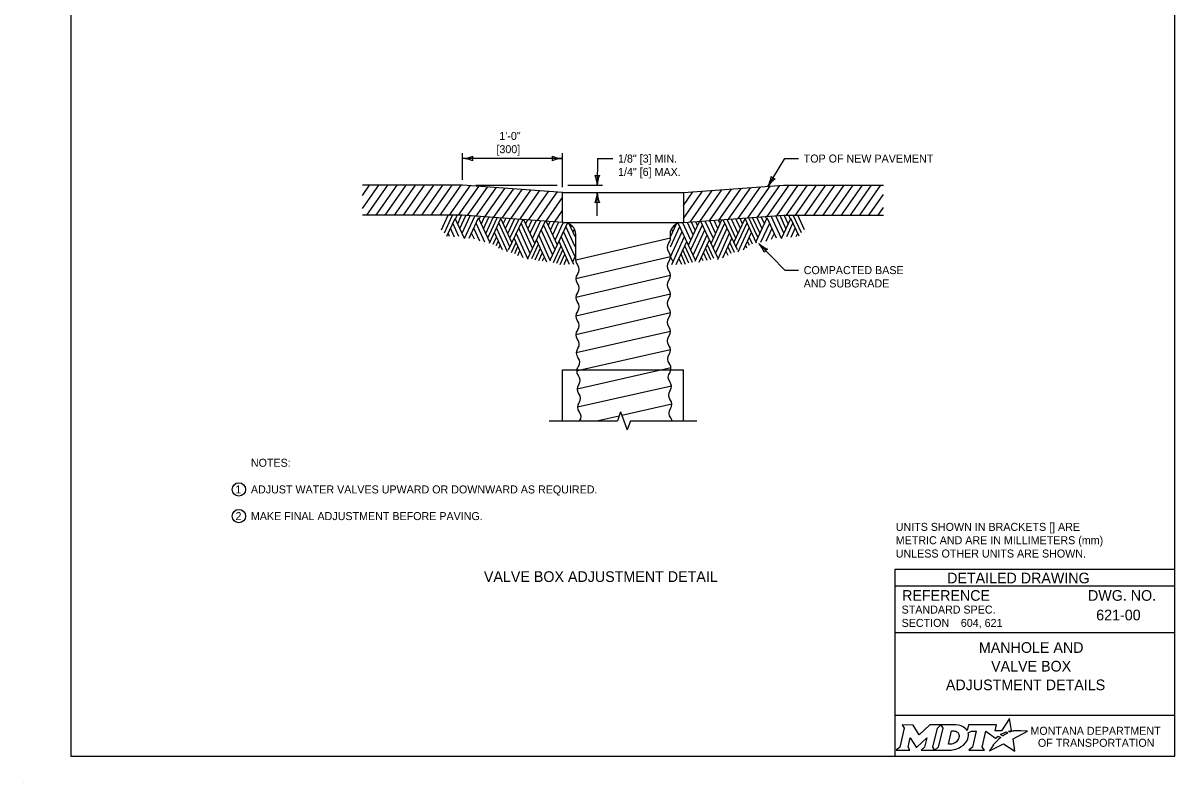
# Model space of a CAD drawing. Extents: x 49991.4 to 50021, y 49987.6 to 50011.4.
# Drawn here: x 49999.98 to 50008.61, y 49999.86 to 50005.56 of the extents above; entities that cross this region are included whole.
import ezdxf

# ---------------------------------------------------------------- set-up
doc = ezdxf.new("R2010")
doc.units = 0
for name, color, linetype in [('Level 1', 7, 'Continuous'), ('Level 2', 7, 'Continuous'), ('Level 3', 7, 'Continuous'), ('Level 4', 7, 'Continuous'), ('Level 6', 7, 'Continuous')]:
    doc.layers.add(name, color=color, linetype=linetype)

msp = doc.modelspace()

# ---------------------------------------------------------------- linework, layer by layer
at = {"layer": 'Level 1'}
for p, q in [((50003.2717, 50004.346), (50002.5217, 50004.346)), ((50002.5217, 50004.2687), (50002.5758, 50004.346)), ((50002.5217, 50004.1707), (50002.6445, 50004.346)), ((50002.5556, 50004.121), (50002.7132, 50004.346)), ((50002.6243, 50004.121), (50002.7818, 50004.346)), ((50002.693, 50004.121), (50002.8506, 50004.346)), ((50002.7616, 50004.121), (50002.9192, 50004.346)), ((50002.8303, 50004.121), (50002.9879, 50004.346)), ((50002.899, 50004.121), (50003.0565, 50004.346)), ((50002.9676, 50004.121), (50003.1252, 50004.346)), ((50003.0363, 50004.121), (50003.1938, 50004.346)), ((50003.105, 50004.121), (50003.2625, 50004.346)), ((50004.0217, 50004.2904), (50003.2717, 50004.346)), ((50004.9285, 50004.2904), (50005.6785, 50004.346)), ((50005.5577, 50004.112), (50005.7215, 50004.346)), ((50005.6301, 50004.1173), (50005.7902, 50004.346)), ((50005.6785, 50004.346), (50006.4285, 50004.346)), ((50005.7014, 50004.121), (50005.8589, 50004.346)), ((50005.77, 50004.121), (50005.9275, 50004.346)), ((50005.8387, 50004.121), (50005.9963, 50004.346)), ((50005.9074, 50004.121), (50006.0649, 50004.346)), ((50005.976, 50004.121), (50006.1336, 50004.346)), ((50006.0447, 50004.121), (50006.2022, 50004.346)), ((50006.1133, 50004.121), (50006.2709, 50004.346)), ((50006.182, 50004.121), (50006.3396, 50004.346)), ((50006.2507, 50004.121), (50006.4082, 50004.346)), ((50003.1736, 50004.121), (50003.3284, 50004.3418)), ((50003.2424, 50004.121), (50003.3935, 50004.337)), ((50003.309, 50004.1182), (50003.4588, 50004.3321)), ((50003.3743, 50004.1133), (50003.5241, 50004.3273)), ((50003.4396, 50004.1085), (50003.5893, 50004.3225)), ((50003.5048, 50004.1037), (50003.6547, 50004.3176)), ((50003.5701, 50004.0988), (50003.7199, 50004.3128)), ((50003.6354, 50004.094), (50003.7853, 50004.3079)), ((50003.7007, 50004.0892), (50003.8505, 50004.3031)), ((50003.766, 50004.0843), (50003.9157, 50004.2983)), ((50003.8312, 50004.0795), (50003.9811, 50004.2934)), ((50004.0217, 50004.2904), (50004.9285, 50004.2904)), ((50004.0217, 50004.0654), (50004.0217, 50004.2904)), ((50004.9285, 50004.0961), (50005.072, 50004.301)), ((50004.9285, 50004.1941), (50004.9995, 50004.2957)), ((50004.9285, 50004.2904), (50004.9285, 50004.0654)), ((50004.9784, 50004.0691), (50005.1444, 50004.3064)), ((50005.0507, 50004.0744), (50005.2169, 50004.3118)), ((50005.1232, 50004.0798), (50005.2894, 50004.3172)), ((50005.1956, 50004.0852), (50005.3618, 50004.3225)), ((50005.2679, 50004.0905), (50005.4343, 50004.3279)), ((50005.3403, 50004.0959), (50005.5066, 50004.3333)), ((50005.4128, 50004.1013), (50005.579, 50004.3386)), ((50005.4853, 50004.1066), (50005.6515, 50004.344)), ((50006.3193, 50004.121), (50006.4285, 50004.2769)), ((50003.8966, 50004.0747), (50004.0217, 50004.2535)), ((50006.3881, 50004.121), (50006.4285, 50004.1788)), ((50003.2707, 50004.121), (50002.5217, 50004.121)), ((50003.1144, 50004.0125), (50003.1645, 50004.121)), ((50003.1361, 50003.9884), (50003.1977, 50004.121)), ((50003.1545, 50003.964), (50003.217, 50004.0974)), ((50003.2863, 50003.9474), (50003.217, 50004.0974)), ((50003.2193, 50004.0924), (50003.2323, 50004.121)), ((50003.2359, 50004.0565), (50003.2653, 50004.121)), ((50003.2529, 50004.0214), (50003.2973, 50004.119)), ((50003.2689, 50003.9856), (50003.3292, 50004.1167)), ((50004.0217, 50004.0654), (50003.2707, 50004.121)), ((50003.2864, 50003.9475), (50003.3637, 50004.1141)), ((50003.3226, 50003.9497), (50003.393, 50004.1008)), ((50003.4773, 50003.9185), (50003.393, 50004.1007)), ((50003.3972, 50004.0916), (50003.4061, 50004.111)), ((50003.4138, 50004.0558), (50003.4379, 50004.1086)), ((50003.4304, 50004.0199), (50003.4699, 50004.1063)), ((50003.4468, 50003.9844), (50003.5027, 50004.1038)), ((50003.4744, 50003.9121), (50003.5596, 50004.0967)), ((50003.4891, 50004.0096), (50003.5313, 50004.1017)), ((50003.6428, 50003.9163), (50003.5596, 50004.0967)), ((50003.5782, 50004.0565), (50003.5967, 50004.0969)), ((50003.5946, 50004.0203), (50003.6286, 50004.0945)), ((50003.6117, 50003.9833), (50003.6618, 50004.092)), ((50003.6168, 50003.8606), (50003.7232, 50004.0875)), ((50003.6281, 50003.9479), (50003.694, 50004.0897)), ((50003.8147, 50003.9095), (50003.7328, 50004.0868)), ((50003.9618, 50004.0698), (50004.0217, 50004.1553)), ((50004.9285, 50004.0654), (50005.6795, 50004.121)), ((50004.9285, 50004.0654), (50005.6795, 50004.121)), ((50005.1355, 50003.9095), (50005.2174, 50004.0868)), ((50005.3334, 50003.8606), (50005.227, 50004.0875)), ((50005.3221, 50003.9479), (50005.2562, 50004.0897)), ((50005.3385, 50003.9833), (50005.2884, 50004.092)), ((50005.3074, 50003.9163), (50005.3906, 50004.0967)), ((50005.3556, 50004.0203), (50005.3216, 50004.0945)), ((50005.372, 50004.0565), (50005.3535, 50004.0969)), ((50005.4758, 50003.9121), (50005.3906, 50004.0967)), ((50005.4611, 50004.0096), (50005.4189, 50004.1017)), ((50005.5034, 50003.9844), (50005.4475, 50004.1038)), ((50005.4729, 50003.9185), (50005.5572, 50004.1007)), ((50005.5198, 50004.0199), (50005.4803, 50004.1063)), ((50005.5364, 50004.0558), (50005.5123, 50004.1086)), ((50005.553, 50004.0916), (50005.5441, 50004.111)), ((50005.6276, 50003.9497), (50005.5572, 50004.1008)), ((50005.6638, 50003.9475), (50005.5865, 50004.1141)), ((50005.6813, 50003.9856), (50005.621, 50004.1167)), ((50005.6973, 50004.0214), (50005.6529, 50004.119)), ((50005.6639, 50003.9474), (50005.7332, 50004.0974)), ((50005.6795, 50004.121), (50006.4285, 50004.121)), ((50005.7143, 50004.0565), (50005.6849, 50004.121)), ((50005.7309, 50004.0924), (50005.7179, 50004.121)), ((50005.7957, 50003.964), (50005.7332, 50004.0974)), ((50005.8141, 50003.9884), (50005.7525, 50004.121)), ((50005.8358, 50004.0125), (50005.7857, 50004.121)), ((50003.2128, 50003.9576), (50003.1824, 50004.0237)), ((50003.2455, 50003.9623), (50003.1999, 50004.0606)), ((50003.4018, 50003.9269), (50003.3569, 50004.0237)), ((50003.4406, 50003.9188), (50003.3744, 50004.061)), ((50003.4621, 50003.9517), (50003.4891, 50004.0096)), ((50003.6104, 50003.847), (50003.5279, 50004.0275)), ((50003.6274, 50003.8834), (50003.5447, 50004.063)), ((50003.7799, 50003.8348), (50003.6933, 50004.0237)), ((50003.7978, 50003.8732), (50003.7108, 50004.0607)), ((50003.7468, 50004.0565), (50003.7596, 50004.0848)), ((50003.7615, 50003.7952), (50003.8918, 50004.075)), ((50003.7638, 50004.0214), (50003.7914, 50004.0825)), ((50003.7798, 50003.9856), (50003.8232, 50004.0801)), ((50003.7972, 50003.9473), (50003.8575, 50004.0776)), ((50003.9485, 50003.8223), (50003.8619, 50004.0112)), ((50003.9664, 50003.8607), (50003.8794, 50004.0482)), ((50003.9833, 50003.897), (50003.9014, 50004.0743)), ((50003.9154, 50004.044), (50003.9282, 50004.0723)), ((50003.9301, 50003.7827), (50004.0597, 50004.0609)), ((50003.9324, 50004.0089), (50003.96, 50004.07)), ((50003.9484, 50003.9731), (50003.9918, 50004.0676)), ((50003.9658, 50003.9348), (50004.0261, 50004.0651)), ((50004.0217, 50004.0654), (50004.9285, 50004.0654)), ((50004.1179, 50003.8851), (50004.048, 50004.0357)), ((50004.1179, 50003.9581), (50004.073, 50004.0554)), ((50004.084, 50004.0315), (50004.0897, 50004.0442)), ((50004.101, 50003.9964), (50004.1109, 50004.0182)), ((50004.8323, 50003.9581), (50004.8772, 50004.0554)), ((50004.8323, 50003.8851), (50004.9022, 50004.0357)), ((50004.8323, 50003.9491), (50004.8323, 50004.0014)), ((50004.8492, 50003.9964), (50004.8393, 50004.0182)), ((50004.8662, 50004.0315), (50004.8605, 50004.0442)), ((50005.0201, 50003.7827), (50004.8905, 50004.0609)), ((50004.9844, 50003.9348), (50004.9241, 50004.0651)), ((50005.0018, 50003.9731), (50004.9584, 50004.0676)), ((50004.9669, 50003.897), (50005.0488, 50004.0743)), ((50004.9838, 50003.8607), (50005.0708, 50004.0482)), ((50005.0178, 50004.0089), (50004.9902, 50004.07)), ((50005.0017, 50003.8223), (50005.0883, 50004.0112)), ((50005.0348, 50004.044), (50005.022, 50004.0723)), ((50005.1887, 50003.7952), (50005.0584, 50004.075)), ((50005.153, 50003.9473), (50005.0927, 50004.0776)), ((50005.1704, 50003.9856), (50005.127, 50004.0801)), ((50005.1524, 50003.8732), (50005.2394, 50004.0607)), ((50005.1864, 50004.0214), (50005.1588, 50004.0825)), ((50005.1703, 50003.8348), (50005.2569, 50004.0237)), ((50005.2034, 50004.0565), (50005.1906, 50004.0848)), ((50005.3228, 50003.8834), (50005.4055, 50004.063)), ((50005.3398, 50003.847), (50005.4223, 50004.0275)), ((50005.4881, 50003.9517), (50005.4611, 50004.0096)), ((50005.5096, 50003.9188), (50005.5758, 50004.061)), ((50005.5484, 50003.9269), (50005.5933, 50004.0237)), ((50005.7047, 50003.9623), (50005.7503, 50004.0606)), ((50005.7374, 50003.9576), (50005.7678, 50004.0237)), ((50003.1752, 50003.9617), (50003.1645, 50003.9852)), ((50003.3608, 50003.9406), (50003.3398, 50003.9863)), ((50003.5026, 50003.9029), (50003.5275, 50003.9573)), ((50003.5713, 50003.8614), (50003.5115, 50003.9925)), ((50003.5257, 50003.8927), (50003.5414, 50003.927)), ((50003.6396, 50003.842), (50003.6737, 50003.9164)), ((50003.7261, 50003.8008), (50003.6585, 50003.9498)), ((50003.7638, 50003.7901), (50003.6754, 50003.9852)), ((50003.9037, 50003.7684), (50003.8271, 50003.9373)), ((50003.9324, 50003.7776), (50003.844, 50003.9727)), ((50004.0749, 50003.7502), (50003.9957, 50003.9248)), ((50004.1077, 50003.7503), (50004.0126, 50003.9602)), ((50004.1179, 50003.8081), (50004.0305, 50003.9987)), ((50004.1217, 50003.7842), (50004.1217, 50003.9754)), ((50004.8323, 50003.9491), (50004.1217, 50003.7842)), ((50004.8323, 50003.8081), (50004.9197, 50003.9987)), ((50004.8425, 50003.7503), (50004.9376, 50003.9602)), ((50004.8753, 50003.7502), (50004.9545, 50003.9248)), ((50005.0178, 50003.7776), (50005.1062, 50003.9727)), ((50005.0465, 50003.7684), (50005.1231, 50003.9373)), ((50005.1864, 50003.7901), (50005.2748, 50003.9852)), ((50005.2241, 50003.8008), (50005.2917, 50003.9498)), ((50005.3106, 50003.842), (50005.2765, 50003.9164)), ((50005.3789, 50003.8614), (50005.4387, 50003.9925)), ((50005.4245, 50003.8927), (50005.4088, 50003.927)), ((50005.4476, 50003.9029), (50005.4227, 50003.9573)), ((50005.5894, 50003.9406), (50005.6104, 50003.9863)), ((50005.775, 50003.9617), (50005.7857, 50003.9852)), ((50003.5448, 50003.8746), (50003.5551, 50003.897)), ((50003.6635, 50003.8328), (50003.6876, 50003.8856)), ((50003.6867, 50003.8186), (50003.7024, 50003.853)), ((50003.7927, 50003.7957), (50003.8423, 50003.9039)), ((50003.8165, 50003.7861), (50003.8562, 50003.8731)), ((50003.8442, 50003.7818), (50003.871, 50003.8405)), ((50003.9536, 50003.7664), (50004.0109, 50003.8914)), ((50003.9798, 50003.7621), (50004.0248, 50003.8606)), ((50004.0052, 50003.7525), (50004.0396, 50003.828)), ((50004.945, 50003.7525), (50004.9106, 50003.828)), ((50004.9704, 50003.7621), (50004.9254, 50003.8606)), ((50004.9966, 50003.7664), (50004.9393, 50003.8914)), ((50005.106, 50003.7818), (50005.0792, 50003.8405)), ((50005.1337, 50003.7861), (50005.094, 50003.8731)), ((50005.1575, 50003.7957), (50005.1079, 50003.9039)), ((50005.2635, 50003.8186), (50005.2478, 50003.853)), ((50005.2867, 50003.8328), (50005.2626, 50003.8856)), ((50005.4054, 50003.8746), (50005.3951, 50003.897)), ((50003.8728, 50003.7779), (50003.8851, 50003.805)), ((50004.0332, 50003.7509), (50004.0525, 50003.7932)), ((50004.0987, 50003.7702), (50004.1179, 50003.8114)), ((50004.8323, 50003.8091), (50004.1217, 50003.6442)), ((50004.8515, 50003.7702), (50004.8323, 50003.8114)), ((50004.917, 50003.7509), (50004.8977, 50003.7932)), ((50005.0774, 50003.7779), (50005.0651, 50003.805)), ((50004.8323, 50003.6691), (50004.1217, 50003.5042)), ((50004.8323, 50003.5291), (50004.1217, 50003.3642)), ((50004.8323, 50003.3891), (50004.1217, 50003.2242)), ((50004.8323, 50003.2491), (50004.1249, 50003.0883)), ((50004.8322, 50003.1117), (50004.1667, 50002.9611)), ((50004.8354, 50002.9758), (50004.7706, 50002.9611)), ((50004.0217, 50002.9611), (50004.9285, 50002.9611)), ((50004.0217, 50002.5787), (50004.0217, 50002.9611)), ((50004.9285, 50002.5787), (50004.9285, 50002.9611)), ((49999.9766, 49999.8624), (49999.9766, 49999.8624))]:
    msp.add_line(p, q, dxfattribs=at)
msp.add_lwpolyline([(50008.6146, 50011.2628), (50000.3356, 50011.2628), (50000.3356, 50000.0624), (50008.6146, 50000.0624)], close=True, dxfattribs=at)
for centre, radius, start, end in [((50004.0317, 50003.9754), 0.09, 0, 90), ((50004.9185, 50003.9754), 0.09, 90, 163.23954), ((50004.8594, 50003.8791), 0.0533, 138.95969, 221.04031), ((50004.779, 50003.9491), 0.0533, 318.95969, 0), ((50004.779, 50003.8091), 0.0533, 318.95969, 41.04031), ((50004.175, 50003.7842), 0.0533, 180, 221.04031), ((50004.0946, 50003.7142), 0.0533, 318.95969, 41.04031), ((50004.8594, 50003.7391), 0.0533, 138.95969, 221.04031), ((50004.175, 50003.6442), 0.0533, 138.95969, 221.04031), ((50004.779, 50003.6691), 0.0533, 318.95969, 41.04031), ((50004.0946, 50003.5742), 0.0533, 318.95969, 41.04031), ((50004.8594, 50003.5991), 0.0533, 138.95969, 221.04031), ((50004.175, 50003.5042), 0.0533, 138.95969, 221.04031), ((50004.8594, 50003.4591), 0.0533, 138.95969, 221.04031), ((50004.779, 50003.5291), 0.0533, 318.95969, 41.04031), ((50004.175, 50003.3642), 0.0533, 138.95969, 221.04031), ((50004.0946, 50003.4342), 0.0533, 318.95969, 41.04031), ((50004.779, 50003.3891), 0.0533, 318.95969, 41.04031), ((50004.0946, 50003.2942), 0.0533, 318.95969, 41.04031), ((50004.8594, 50003.3191), 0.0533, 138.95969, 221.04031), ((50004.175, 50003.2242), 0.0533, 138.95969, 221.04031), ((50004.779, 50003.2491), 0.0533, 318.95969, 41.04031), ((50004.0946, 50003.1542), 0.0533, 324.57936, 41.04031), ((50004.8594, 50003.1791), 0.0533, 138.95969, 221.04031), ((50004.779, 50003.1091), 0.0533, 324.57936, 41.04031), ((50004.1782, 50003.0883), 0.0533, 138.95969, 221.04031), ((50004.0978, 50003.0183), 0.0533, 324.57936, 41.04031), ((50004.8626, 50003.0432), 0.0533, 138.95969, 221.04031), ((50004.1814, 50002.9524), 0.0533, 138.95969, 170.60676), ((50004.7822, 50002.9732), 0.0533, 346.87993, 41.04031)]:
    msp.add_arc(centre, radius, start, end, dxfattribs=at)
at = {"layer": 'Level 2'}
for p, q in [((50008.6146, 50001.4624), (50006.5146, 50001.4624)), ((50006.5146, 50001.4624), (50006.5146, 50000.0624)), ((50008.6146, 50001.3374), (50006.5146, 50001.3374)), ((50008.2507, 50001.1223), (50008.2507, 50001.1223)), ((50008.6146, 50000.9874), (50006.5146, 50000.9874)), ((50007.0089, 50001.0629), (50007.0089, 50001.0629)), ((50007.5646, 50000.7383), (50007.5646, 50000.7383)), ((50008.6146, 50000.3693), (50006.5146, 50000.3693))]:
    msp.add_line(p, q, dxfattribs=at)
for points in [[(50006.5701, 50000.2974), (50006.5842, 50000.274), (50006.5507, 50000.1307), (50006.525, 50000.1082), (50006.6266, 50000.1082), (50006.6131, 50000.131), (50006.6293, 50000.2011), (50006.673, 50000.1321), (50006.6783, 50000.1321), (50006.7534, 50000.2016), (50006.737, 50000.1305), (50006.7123, 50000.1085), (50006.8139, 50000.1085), (50006.8001, 50000.1318), (50006.8333, 50000.2742)], [(50006.8333, 50000.2742), (50006.8586, 50000.2974), (50006.7762, 50000.2974), (50006.6966, 50000.2244), (50006.6521, 50000.2971), (50006.5701, 50000.2974)], [(50006.9722, 50000.2974), (50006.8586, 50000.2974), (50006.8733, 50000.2745), (50006.8394, 50000.1307), (50006.8139, 50000.1085), (50006.9245, 50000.1085)], [(50007.3771, 50000.2447), (50007.3668, 50000.2503), (50007.3784, 50000.2531), (50007.39, 50000.2551), (50007.3726, 50000.3452), (50007.3131, 50000.2539), (50007.2658, 50000.2532), (50007.2761, 50000.2973), (50007.0669, 50000.2974), (50007.0568, 50000.2549), (50007.051, 50000.2632)], [(50006.9962, 50000.2107), (50006.995, 50000.2026), (50006.9918, 50000.1933), (50006.9876, 50000.1851), (50006.982, 50000.1776), (50006.9755, 50000.1707), (50006.9676, 50000.1644), (50006.9593, 50000.1597), (50006.9502, 50000.1558), (50006.9411, 50000.1535), (50006.9319, 50000.1526), (50006.916, 50000.1526), (50006.9396, 50000.2526), (50006.9556, 50000.2526), (50006.9632, 50000.252), (50006.9708, 50000.2501), (50006.9774, 50000.2471), (50006.9835, 50000.2429), (50006.9883, 50000.2379), (50006.992, 50000.2319), (50006.9947, 50000.2257), (50006.9963, 50000.2183), (50006.9963, 50000.2153), (50006.9962, 50000.2107)], [(50007.0636, 50000.2383), (50007.0882, 50000.2514), (50007.1251, 50000.2514), (50007.0965, 50000.1309), (50007.069, 50000.1082), (50007.1852, 50000.1082), (50007.1682, 50000.1311), (50007.1964, 50000.2513), (50007.2677, 50000.1996), (50007.2888, 50000.2147), (50007.3085, 50000.2038)], [(50007.2527, 50000.1479), (50007.2374, 50000.1235), (50007.2327, 50000.116), (50007.2269, 50000.1074), (50007.2246, 50000.1031), (50007.3299, 50000.1562), (50007.4138, 50000.1011), (50007.4007, 50000.1938), (50007.5076, 50000.2522), (50007.4583, 50000.253), (50007.4282, 50000.2534), (50007.4074, 50000.2537), (50007.4006, 50000.2522), (50007.3957, 50000.251), (50007.3873, 50000.2487), (50007.3771, 50000.2447)], [(50007.3267, 50000.2171), (50007.3243, 50000.2154), (50007.306, 50000.225), (50007.3163, 50000.2307), (50007.3204, 50000.2329), (50007.329, 50000.2369), (50007.3347, 50000.2395), (50007.3426, 50000.2425), (50007.3499, 50000.2452), (50007.3617, 50000.2378), (50007.3577, 50000.2357), (50007.3531, 50000.2332), (50007.3489, 50000.231), (50007.3439, 50000.2281), (50007.342, 50000.227), (50007.3393, 50000.2254), (50007.3368, 50000.224), (50007.3345, 50000.2224), (50007.3319, 50000.2206), (50007.3292, 50000.2188), (50007.3267, 50000.2171)], [(50006.9702, 50000.1158), (50006.9786, 50000.1184), (50006.9916, 50000.1238), (50007.012, 50000.1348)], [(50007.2666, 50000.164), (50007.2666, 50000.164)]]:
    msp.add_lwpolyline(points, dxfattribs=at)
for centre in [(50001.5952, 50002.0642), (50001.5952, 50001.8642)]:
    msp.add_circle(centre, 0.05, dxfattribs=at)
for centre, radius, start, end in [((50006.9953, 50000.219), 0.0709, 339.53292, 15.85821), ((50006.9513, 50000.2363), 0.1183, 300.91025, 339.13831)]:
    msp.add_arc(centre, radius, start, end, dxfattribs=at)
for centre, major_axis, ratio, start_param, end_param in [((50006.9701, 50000.25), (0.0834, -0.0037), 0.568097, 0.61298, 1.570796), ((50007.0257, 50000.2573), (0.0361, -0.0295), 0.469099, 1.225588, 1.570796), ((50007.2974, 50000.1941), (-0.0112, -0.0097), 0.021651, 3.157348, 6.283185), ((50006.9248, 50000.2568), (0, 0.1484), 0.987302, 3.139398, 3.456847), ((50007.2597, 50000.1559), (-0.00694, -0.00806), 0.008222, 0, 3.137361), ((50007.2764, 50000.1742), (-0.0098, -0.0102), 0.016458, 3.141593, 6.279097)]:
    msp.add_ellipse(centre, major_axis=major_axis, ratio=ratio, start_param=start_param, end_param=end_param, dxfattribs=at)
at = {"layer": 'Level 3'}
for p, q in [((50003.2717, 50004.386), (50003.2717, 50004.586)), ((50004.0217, 50004.546), (50003.2717, 50004.546)), ((50004.0217, 50004.3304), (50004.0217, 50004.586)), ((50004.2832, 50004.546), (50004.2829, 50004.346)), ((50004.2832, 50004.546), (50004.3983, 50004.5459)), ((50005.562, 50004.3374), (50005.688, 50004.546)), ((50005.688, 50004.546), (50005.7907, 50004.546)), ((50003.3717, 50004.346), (50003.9817, 50004.346)), ((50004.0617, 50004.346), (50004.3229, 50004.346)), ((50004.2829, 50004.117), (50004.2829, 50004.2904)), ((50005.494, 50003.9094), (50005.688, 50003.7093)), ((50005.688, 50003.7093), (50005.7907, 50003.7093))]:
    msp.add_line(p, q, dxfattribs=at)
for centre, radius, start, end in [((50003.2602, 50004.7787), 0.233, 272.82731, 292.07716), ((50003.2625, 50004.3239), 0.2223, 67.45601, 87.63952), ((50003.3999, 50004.546), 0.0548, 162.13882, 197.86118), ((50004.0309, 50004.7681), 0.2223, 247.45601, 267.63952), ((50003.8935, 50004.546), 0.0548, 342.13882, 17.86118), ((50004.0332, 50004.3133), 0.233, 92.82731, 112.07716), ((50004.2829, 50004.4742), 0.0548, 252.13882, 287.86118), ((50004.0502, 50004.3345), 0.233, 2.82731, 22.07716), ((50004.505, 50004.3368), 0.2223, 157.45601, 177.63952), ((50005.3568, 50004.4478), 0.233, 331.69421, 350.94406), ((50005.7474, 50004.2147), 0.2223, 126.32291, 146.50642), ((50005.6283, 50004.4471), 0.0548, 221.00572, 256.72808), ((50004.0608, 50004.2996), 0.2223, 337.45601, 357.63952), ((50004.5156, 50004.3019), 0.233, 182.82731, 202.07716), ((50004.2829, 50004.1622), 0.0548, 72.13882, 107.86118), ((50005.3281, 50003.7614), 0.2223, 21.56924, 41.75275), ((50005.6531, 50004.0796), 0.233, 226.94054, 246.19039), ((50005.5832, 50003.8173), 0.0548, 116.25205, 151.97441)]:
    msp.add_arc(centre, radius, start, end, dxfattribs=at)
at = {"layer": 'Level 4'}
for p, q in [((50004.1667, 50002.9611), (50004.1281, 50002.9524)), ((50004.7704, 50002.9611), (50004.1313, 50002.8165)), ((50004.8386, 50002.8399), (50004.1345, 50002.6806)), ((50004.8418, 50002.704), (50004.468, 50002.619)), ((50004.4462, 50002.6141), (50004.2906, 50002.5787))]:
    msp.add_line(p, q, dxfattribs=at)
for centre, start, end in [((50004.1814, 50002.9524), 170.60676, 221.04031), ((50004.101, 50002.8824), 324.57936, 41.04031), ((50004.8658, 50002.9073), 138.95969, 221.04031), ((50004.7822, 50002.9732), 324.57936, 346.87993), ((50004.1846, 50002.8165), 138.95969, 221.04031), ((50004.869, 50002.7714), 138.95969, 221.04031), ((50004.7854, 50002.8373), 324.57936, 41.04031), ((50004.1878, 50002.6806), 138.95969, 221.04031), ((50004.1042, 50002.7465), 324.57936, 41.04031), ((50004.7886, 50002.7014), 324.57936, 41.04031), ((50004.1074, 50002.6106), 323.24212, 41.04031), ((50004.8722, 50002.6355), 138.95969, 221.04031), ((50004.7918, 50002.5655), 14.33721, 41.04031)]:
    msp.add_arc(centre, 0.0533, start, end, dxfattribs=at)
at = {"layer": 'Level 6'}
for p, q in [((50004.4579, 50002.6473), (50004.4337, 50002.5787)), ((50004.4579, 50002.6473), (50004.4823, 50002.5787)), ((50003.9217, 50002.5787), (50004.4337, 50002.5787)), ((50004.4823, 50002.5787), (50004.5065, 50002.5101)), ((50004.5309, 50002.5787), (50004.5065, 50002.5101)), ((50004.5309, 50002.5787), (50005.0285, 50002.5787))]:
    msp.add_line(p, q, dxfattribs=at)

# ---------------------------------------------------------------- texts
at = {"layer": 'Level 2'}
for s, height, p in [('1\'-0"', 0.06, (50003.5483, 50004.686)), ('[300]', 0.06, (50003.5265, 50004.586)), ('1/8" [3] MIN.', 0.06, (50004.4383, 50004.5159)), ('TOP OF NEW PAVEMENT', 0.06, (50005.8307, 50004.516)), ('1/4" [6] MAX.', 0.06, (50004.4383, 50004.4159)), ('COMPACTED BASE', 0.06, (50005.8307, 50003.6793)), ('AND SUBGRADE', 0.06, (50005.8307, 50003.5793)), ('NOTES:', 0.06, (50001.6852, 50002.2342)), ('1', 0.06, (50001.5688, 50002.0342)), ('ADJUST WATER VALVES UPWARD OR DOWNWARD AS REQUIRED.', 0.06, (50001.6852, 50002.0342)), ('2', 0.06, (50001.57, 50001.8342)), ('MAKE FINAL ADJUSTMENT BEFORE PAVING.', 0.06, (50001.6852, 50001.8342)), ('UNITS SHOWN IN BRACKETS [] ARE ', 0.06, (50006.5208, 50001.7533)), ('METRIC AND ARE IN MILLIMETERS (mm) ', 0.06, (50006.5208, 50001.6533)), ('UNLESS OTHER UNITS ARE SHOWN.', 0.06, (50006.5208, 50001.5533)), ('VALVE BOX ADJUSTMENT DETAIL', 0.08, (50003.4325, 50001.3702)), ('DETAILED DRAWING', 0.0799, (50006.9063, 50001.3599)), ('REFERENCE', 0.08, (50006.5682, 50001.229)), ('DWG. NO.', 0.08, (50007.9624, 50001.229)), ('STANDARD SPEC.', 0.06, (50006.5649, 50001.133)), ('621-00', 0.08, (50008.0241, 50001.0823)), ('SECTION', 0.06, (50006.5649, 50001.033)), ('604, 621', 0.06, (50007.0089, 50001.0329)), ('MANHOLE AND', 0.08, (50007.1443, 50000.8383)), ('VALVE BOX', 0.08, (50007.2358, 50000.6983)), ('ADJUSTMENT DETAILS', 0.08, (50006.8968, 50000.5583)), ('MONTANA DEPARTMENT', 0.06, (50007.5308, 50000.2236)), ('OF TRANSPORTATION', 0.06, (50007.587, 50000.1336))]:
    msp.add_text(s, height=height, dxfattribs=at).set_placement(p)

doc.saveas('drawing.dxf')
